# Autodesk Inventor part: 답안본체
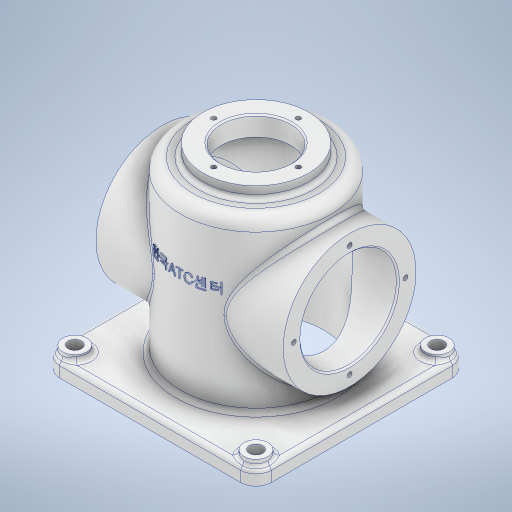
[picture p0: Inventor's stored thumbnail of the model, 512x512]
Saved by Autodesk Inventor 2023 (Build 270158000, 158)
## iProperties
Created: 2025-05
Part Number: 답안본체
Material: 알루미늄 6061
Document SubType Name: Modeling
Designer: ADMIN_PC
Density: 2.7 g/cm^3
Appearance: 알루미늄 - 평지
Mass: 1092.86 g
Surface Area: 1204.83 cm^2
Volume: 404.763 cm^3
Author: ADMIN_PC
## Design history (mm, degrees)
sketch "스케치1"
  geometry: L1 (-70, 70)-(70, 70); L2 (70, 70)-(70, -70); L3 (70, -70)-(-70, -70); L4 (-70, -70)-(-70, 70); L5 (-70, 70)-(70, -70); L6 (70, 70)-(-70, -70); 1 further point
  constraints: 12 end point, 2 midpoint, 2 parallel, 1 horizontal, 1 perpendicular
  dimensions: "d0" = 140 distance of L2.end L3.end; "d1" = 140 distance of L1.end L2.end
extrude "돌출1" new body sketch "스케치1" distance "d2" = 10; taper "d3" = 0 deg
sketch "스케치2"
  geometry: C1 r 50 at (0, 0); 1 further point
  constraints: 1 centre point, 1 coincident
  dimensions: "d4" = 100 diameter of C1
extrude "돌출2" join sketch "스케치2" distance "d5" = 112; taper "d6" = 0 deg
fillet "모깎기1" dims "d10" = 8
fillet "모깎기2" dims "d11" = 3
node "작업 평면1"
sketch "스케치4"
  geometry: L1 (0, 70)-(0, -70) reference; C1 r 44 at (65, 0); 3 further points
  constraints: 2 horizontal alignment, 2 midpoint, 1 centre point
  dimensions: "d13" = 88 diameter of C1; "d14" = 65 distance from line of L1 C1.centre
extrude "돌출4" join sketch "스케치4" distance "d15" = 124; taper "d16" = 0 deg
fillet "모깎기3" dims "d17" = 3
sketch "스케치5"
  geometry: L1 (-70, -65)-(70, -65) reference; C1 r 32 at (0, 0); 2 further points
  constraints: 1 centre point, 1 midpoint, 1 vertical alignment
  dimensions: "d18" = 64 diameter of C1; "d19" = 65 distance from line of L1 C1.centre
extrude "돌출5" cut sketch "스케치5" distance "d20" = 124; taper "d21" = 0 deg
sketch "스케치6" dims "d22" = 74
  geometry: C1 r 32 at (0, 0) reference; 3 further points
  constraints: 2 vertical alignment, 1 coincident, 2 other
hole "구멍1" sketch "스케치6" at (0, 37) diameter "d23" = 3.242; stored, may be unused: countersink angle "d27" = 90 deg, drill point angle "d29" = 118 deg; dims "d24" = 8, "d25" = 4, "d26" = 2, "d28" = 10
sketch "스케치7"
  geometry: C1 r 35 at (0, 0); 1 further point
  constraints: 1 centre point, 1 coincident
  dimensions: "d33" = 70 diameter of C1
extrude "돌출6" join sketch "스케치7" distance "d34" = 8; taper "d35" = 0 deg
sketch "스케치8"
  geometry: C1 r 23 at (0, 0); 1 further point
  constraints: 1 centre point, 1 coincident
  dimensions: "d36" = 46 diameter of C1
extrude "돌출7" cut sketch "스케치8" extent not by distance; stored distance "d37" = 0; taper "d38" = 0 deg
sketch "스케치9"
  geometry: C1 r 35 at (0, 0) reference; C2 r 45 at (0, 0); 1 further point
  constraints: 1 centre point, 1 coincident
  dimensions: "d39" = 90 diameter of C2
extrude "돌출8" cut sketch "스케치9" distance "d40" = 117; taper "d41" = 0 deg
sketch "스케치10" dims "d42" = 56
  geometry: C1 r 23 at (0, 0) reference; 3 further points
  constraints: 2 vertical alignment, 1 coincident, 2 other
hole "구멍2" sketch "스케치10" at (0, 28) diameter "d43" = 3.242; stored, may be unused: countersink angle "d47" = 90 deg, drill point angle "d49" = 118 deg; dims "d44" = 8, "d45" = 4, "d46" = 2, "d48" = 10
fillet "모깎기4" dims "d53" = 3
chamfer "모따기1" distance "d54" = 1; stored, may be unused: second distance "d55" = 2, angle "d56" = 45 deg
fillet "모깎기6" dims "d72" = 3
node "작업 평면2"
sketch "스케치13"
  geometry: L1 (-70, 0)-(70, 0) reference; 2 further points
  constraints: 1 other
  dimensions: "d77" = 80 distance from line of L1 point (-0.204, 80)
feature "엠보싱1" sketch "스케치13" dims "d0" = 140, "d1" = 140, "d78" = 0.5, "d79" = 0
chamfer "모따기3" distance "d80" = 1; stored, may be unused: second distance "d81" = 2, angle "d82" = 45 deg
fillet "모깎기7" dims "d83" = 3
fillet "모깎기9" dims "d85" = 10
sketch "스케치14"
  geometry: L1 (60, -60)-(-60, -60); L2 (-60, -60)-(-60, 60); L3 (-60, 60)-(60, 60); L4 (60, 60)-(60, -60); L5 (60, -60)-(-60, 60); L6 (-60, -60)-(60, 60); C1 r 8 at (-60, -60); C2 r 8 at (-60, 60); C3 r 8 at (60, 60); C4 r 8 at (60, -60); 1 further point
  constraints: 12 end point, 4 centre point, 4 coincident, 2 midpoint, 2 parallel, 1 horizontal, 1 perpendicular
  dimensions: "d86" = 120 distance of L2.end L3.end; "d87" = 120 distance of L1.end L2.end; "d88" = 16 diameter of C1; "d89" = 16 diameter of C2; "d90" = 16 diameter of C3; "d91" = 16 diameter of C4
extrude "돌출11" join sketch "스케치14" distance "d92" = 4; taper "d93" = 0 deg
sketch "스케치16"
  geometry: L1 (60, -60)-(-60, -60); L2 (-60, -60)-(-60, 60); L3 (-60, 60)-(60, 60); L4 (60, 60)-(60, -60); L5 (60, -60)-(-60, 60); L6 (-60, -60)-(60, 60); C1 r 4.5 at (-60, -60); C2 r 4.5 at (-60, 60); C3 r 4.5 at (60, 60); C4 r 4.5 at (60, -60); 1 further point
  constraints: 12 end point, 4 centre point, 4 coincident, 2 midpoint, 2 parallel, 1 horizontal, 1 perpendicular
  dimensions: "d95" = 120 distance of L2.end L3.end; "d96" = 120 distance of L1.end L2.end; "d97" = 9 diameter of C1; "d98" = 9 diameter of C2; "d99" = 9 diameter of C3; "d100" = 9 diameter of C4
extrude "돌출12" cut sketch "스케치16" extent not by distance; stored distance "d101" = 0; taper "d102" = 0 deg
fillet "모깎기10" dims "d103" = 3
node "솔리드1"
pattern_circular "원형 패턴1" dims angle "d31" = 360 deg
mirror "미러1"
pattern_circular "원형 패턴2" dims angle "d51" = 360 deg
feature "A9D066F2-1C7D-4E18-AEED-F7BC21143FA4" dims "d43" = 3.242, "d44" = 8, "d45" = 4, "d46" = 2, "d47" = 90 deg, "d48" = 10, "d49" = 118 deg
other parameters: "d12" = 62
